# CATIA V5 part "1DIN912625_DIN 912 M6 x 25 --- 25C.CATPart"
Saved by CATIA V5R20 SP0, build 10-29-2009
Part number: 1DIN912625_DIN 912 M6 x 25 --- 25C
Revision: ANY
Definition: UNKNOWN
Nomenclature: 1DIN912625_DIN 912 M6 x 25 --- 25C
Source: Unknown
Bounding box of the stored display mesh (mm): x 0 to 31, y -5 to 5, z -5 to 5
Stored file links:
  C:\Users\Utente\Desktop\IO LAVORO\3D X SITO CF\CUMSA\3D files CG\CG 603035\1DIN912625_DIN 912 M6 x 25 --- 25C.CATPart
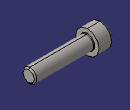
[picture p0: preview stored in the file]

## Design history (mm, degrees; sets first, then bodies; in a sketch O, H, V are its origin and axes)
Body1 "Hex" (main body)
  Solid1: solid without history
